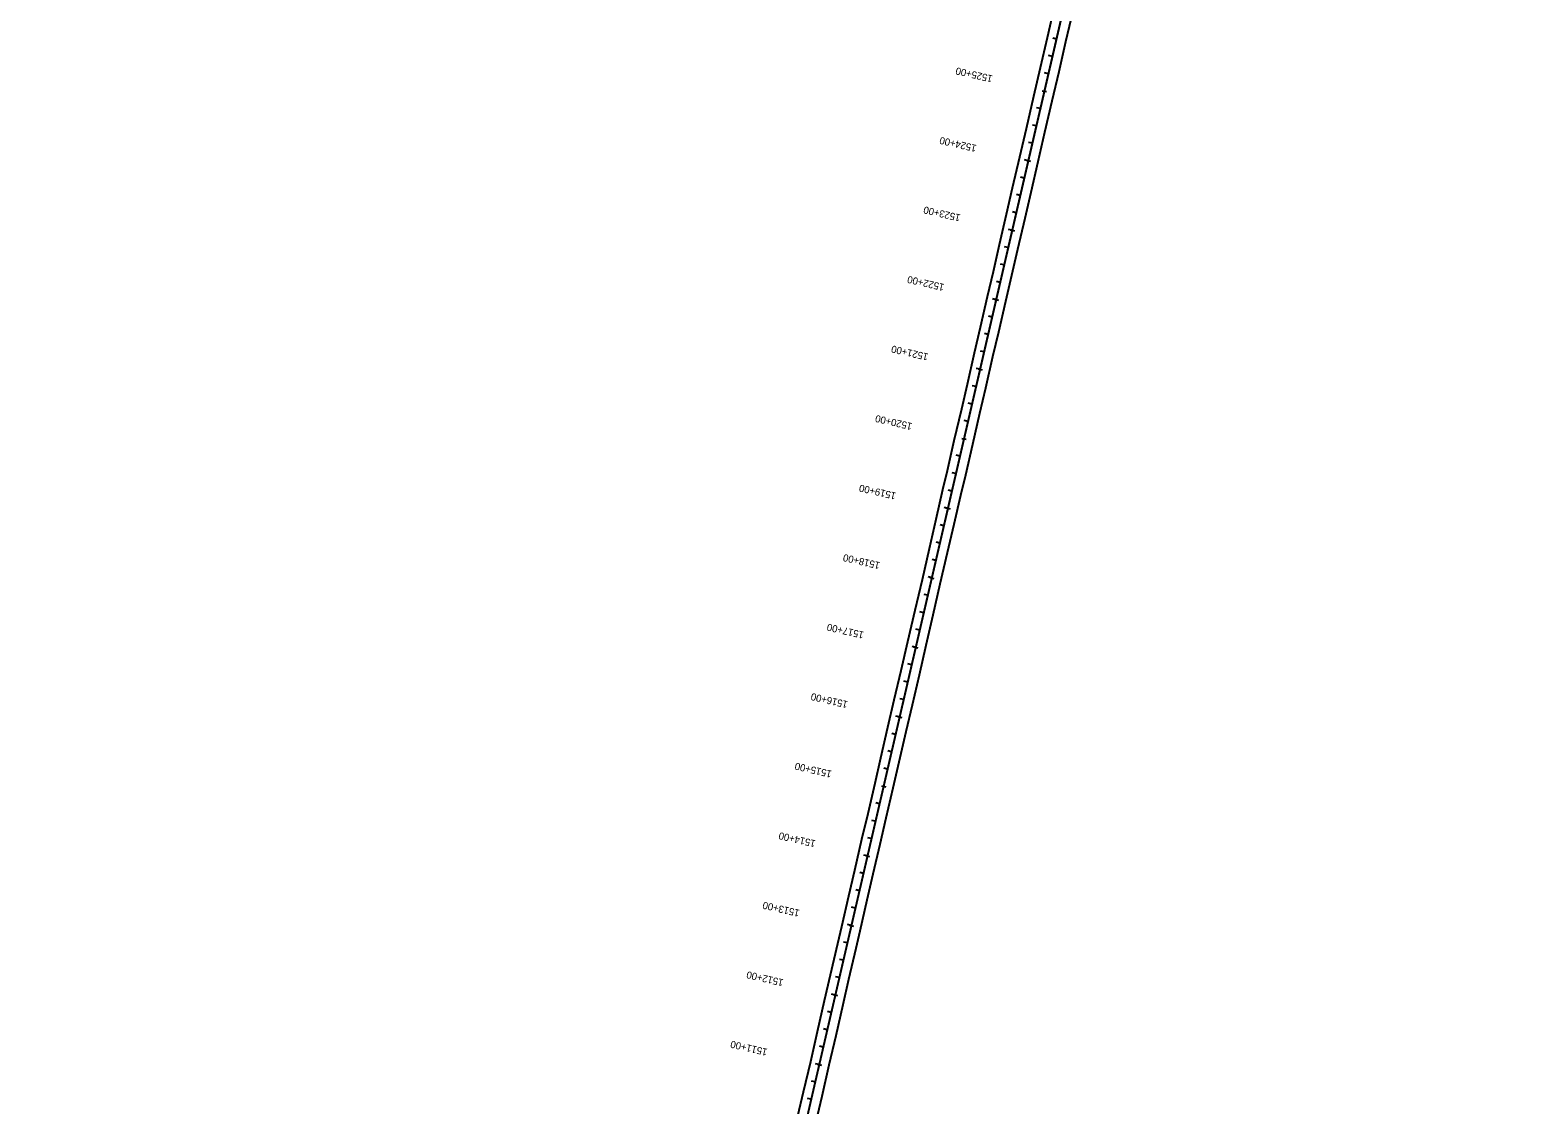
# Model space of a CAD drawing. Extents: x 21596470 to 21601942, y 8263806 to 8275912.
# Drawn here: x 21596601 to 21598714, y 8271376 to 8272882 of the extents above; entities that cross this region are included whole.
import ezdxf

# ---------------------------------------------------------------- set-up
doc = ezdxf.new("R2010")
doc.units = 0
for name, color, linetype in [('Level 1', 7, 'Continuous'), ('Level 20', 7, 'Continuous'), ('SurTxtLeaderLine', 7, 'Continuous'), ('SurTxtSurveyInformation', 7, 'Continuous'), ('wetNoteSoil', 7, 'Continuous')]:
    doc.layers.add(name, color=color, linetype=linetype)

msp = doc.modelspace()

# ---------------------------------------------------------------- linework, layer by layer
at = {"layer": 'Level 1'}
for p, q in [((21598019.8, 8272796.9), (21598025.8, 8272795.6)), ((21598000.3, 8272698.8), (21597994.9, 8272700.1)), ((21597977.7, 8272601.4), (21597972.4, 8272602.6)), ((21597955.2, 8272504), (21597949.9, 8272505.2)), ((21597932.6, 8272406.5), (21597927.3, 8272407.8)), ((21597907.1, 8272309.8), (21597913.1, 8272308.4)), ((21597887.6, 8272211.7), (21597882.2, 8272212.9)), ((21597865, 8272114.3), (21597859.7, 8272115.5)), ((21597842.5, 8272016.8), (21597837.2, 8272018.1)), ((21597819.9, 8271919.4), (21597814.6, 8271920.6)), ((21597794.4, 8271822.7), (21597800.4, 8271821.3)), ((21597774.9, 8271724.6), (21597769.5, 8271725.8)), ((21597752.3, 8271627.1), (21597747, 8271628.4)), ((21597729.8, 8271529.7), (21597724.5, 8271530.9)), ((21597707.2, 8271432.3), (21597701.9, 8271433.5))]:
    msp.add_line(p, q, dxfattribs=at)
at = {"layer": 'Level 20'}
for p, q in [((21596601.4, 8266652.3), (21598714.2, 8275785)), ((21596728.7, 8267202.6), (21598588.8, 8275242.6))]:
    msp.add_line(p, q, dxfattribs=at)
at = {"layer": 'SurTxtLeaderLine'}
msp.add_lwpolyline([(21597702.9, 8271352.7), (21597711.1, 8271388.2), (21597721, 8271431.7), (21597730.7, 8271473.1), (21597740.7, 8271516.5), (21597748.7, 8271551.9), (21597759, 8271595.4), (21597764.4, 8271619.7), (21597774.5, 8271663.2), (21597782.9, 8271699.4), (21597792.7, 8271741.1), (21597801.1, 8271777.8), (21597811, 8271820.1), (21597819.3, 8271856.4), (21597829, 8271898.9), (21597837.8, 8271936.2), (21597847.5, 8271978.2), (21597857.2, 8272020.1), (21597866.9, 8272062.3), (21597876.9, 8272105.9), (21597887.1, 8272149.6), (21597896.4, 8272189.7), (21597905.8, 8272230.2), (21597912.6, 8272258.8), (21597922.3, 8272301.6), (21597932.2, 8272344.9), (21597940.6, 8272380.6), (21597950.6, 8272424.3), (21597958.9, 8272459.1), (21597968.8, 8272502.2), (21597977.1, 8272538.3), (21597985.7, 8272575.1), (21597995.6, 8272618.1), (21598004.1, 8272654.8), (21598013.9, 8272697.5), (21598023.5, 8272738.7), (21598033.7, 8272782.6), (21598043.2, 8272823.7), (21598052.9, 8272865.9), (21598062.9, 8272908.8)], dxfattribs=at)
at = {"layer": 'SurTxtSurveyInformation'}
msp.add_lwpolyline([(21597677.4, 8271360.4), (21597685.2, 8271394.3), (21597695.2, 8271436.7), (21597704.9, 8271478.6), (21597714.8, 8271522), (21597722.9, 8271557.8), (21597733.3, 8271601.7), (21597739.1, 8271625.9), (21597748.9, 8271668.9), (21597757.1, 8271704.8), (21597767.1, 8271748.1), (21597775.6, 8271784.2), (21597785.4, 8271826.4), (21597793.6, 8271862.2), (21597803.5, 8271905.2), (21597812.3, 8271943.2), (21597822.2, 8271984.3), (21597831.5, 8272025), (21597841.7, 8272069), (21597851.7, 8272111.9), (21597861.7, 8272155.4), (21597871.2, 8272196.4), (21597880.6, 8272238.1), (21597886.9, 8272264.5), (21597896.5, 8272306.9), (21597907.1, 8272351.3), (21597914.9, 8272385.5), (21597925, 8272429.8), (21597933.1, 8272465.5), (21597943.1, 8272508.5), (21597951.2, 8272543.8), (21597959.7, 8272581.6), (21597969.4, 8272624), (21597978.2, 8272660.6), (21597988.3, 8272704.2), (21597997.5, 8272744), (21598007.9, 8272789.3), (21598017.1, 8272829.3), (21598027.1, 8272871.6), (21598036.9, 8272914.3)], dxfattribs=at)
at = {"layer": 'wetNoteSoil'}
for p, q in [((21598039.7, 8272869.3), (21598034.4, 8272870.5)), ((21598034.1, 8272845), (21598028.7, 8272846.2)), ((21598028.4, 8272820.6), (21598023.1, 8272821.8)), ((21598019.8, 8272796.9), (21598025.8, 8272795.6)), ((21598017.2, 8272771.9), (21598011.8, 8272773.1)), ((21598011.5, 8272747.5), (21598006.2, 8272748.8)), ((21598005.9, 8272723.2), (21598000.6, 8272724.4)), ((21597997.3, 8272699.5), (21598003.2, 8272698.1)), ((21597994.6, 8272674.5), (21597989.3, 8272675.7)), ((21597989, 8272650.1), (21597983.7, 8272651.3)), ((21597983.4, 8272625.7), (21597978, 8272627)), ((21597974.7, 8272602.1), (21597980.7, 8272600.7)), ((21597972.1, 8272577), (21597966.8, 8272578.3)), ((21597966.4, 8272552.7), (21597961.1, 8272553.9)), ((21597960.8, 8272528.3), (21597955.5, 8272529.6)), ((21597952.2, 8272504.7), (21597958.2, 8272503.3)), ((21597949.5, 8272479.6), (21597944.2, 8272480.8)), ((21597943.9, 8272455.3), (21597938.6, 8272456.5)), ((21597938.3, 8272430.9), (21597933, 8272432.1)), ((21597929.7, 8272407.2), (21597935.6, 8272405.8)), ((21597927, 8272382.2), (21597921.7, 8272383.4)), ((21597921.4, 8272357.8), (21597916, 8272359.1)), ((21597915.7, 8272333.5), (21597910.4, 8272334.7)), ((21597907.1, 8272309.8), (21597913.1, 8272308.4)), ((21597904.5, 8272284.8), (21597899.1, 8272286)), ((21597898.8, 8272260.4), (21597893.5, 8272261.6)), ((21597893.2, 8272236), (21597887.9, 8272237.3)), ((21597884.6, 8272212.4), (21597890.5, 8272211)), ((21597881.9, 8272187.3), (21597876.6, 8272188.6)), ((21597876.3, 8272163), (21597871, 8272164.2)), ((21597870.7, 8272138.6), (21597865.3, 8272139.8)), ((21597862, 8272114.9), (21597868, 8272113.6)), ((21597859.4, 8272089.9), (21597854.1, 8272091.1)), ((21597853.8, 8272065.5), (21597848.4, 8272066.8)), ((21597848.1, 8272041.2), (21597842.8, 8272042.4)), ((21597839.5, 8272017.5), (21597845.5, 8272016.1)), ((21597836.8, 8271992.5), (21597831.5, 8271993.7)), ((21597831.2, 8271968.1), (21597825.9, 8271969.3)), ((21597825.6, 8271943.8), (21597820.3, 8271945)), ((21597817, 8271920.1), (21597822.9, 8271918.7)), ((21597814.3, 8271895), (21597809, 8271896.3)), ((21597808.7, 8271870.7), (21597803.4, 8271871.9)), ((21597803, 8271846.3), (21597797.7, 8271847.6)), ((21597794.4, 8271822.7), (21597800.4, 8271821.3)), ((21597791.8, 8271797.6), (21597786.4, 8271798.9)), ((21597786.1, 8271773.3), (21597780.8, 8271774.5)), ((21597780.5, 8271748.9), (21597775.2, 8271750.1)), ((21597771.9, 8271725.2), (21597777.8, 8271723.9)), ((21597769.2, 8271700.2), (21597763.9, 8271701.4)), ((21597763.6, 8271675.8), (21597758.3, 8271677.1)), ((21597758, 8271651.5), (21597752.6, 8271652.7)), ((21597749.3, 8271627.8), (21597755.3, 8271626.4)), ((21597746.7, 8271602.8), (21597741.4, 8271604)), ((21597741.1, 8271578.4), (21597735.7, 8271579.6)), ((21597735.4, 8271554.1), (21597730.1, 8271555.3)), ((21597726.8, 8271530.4), (21597732.8, 8271529)), ((21597724.1, 8271505.3), (21597718.8, 8271506.6)), ((21597718.5, 8271481), (21597713.2, 8271482.2)), ((21597712.9, 8271456.6), (21597707.6, 8271457.9)), ((21597704.3, 8271433), (21597710.2, 8271431.6)), ((21597701.6, 8271407.9), (21597696.3, 8271409.1)), ((21597696, 8271383.6), (21597690.7, 8271384.8))]:
    msp.add_line(p, q, dxfattribs=at)

# ---------------------------------------------------------------- texts
at = {"layer": 'Level 1'}
for s, p in [('1525+00', (21597950.9, 8272818)), ('1520+00', (21597838.2, 8272330.9)), ('1515+00', (21597725.5, 8271843.8))]:
    msp.add_text(s, height=10.02, rotation=166.974, dxfattribs=at).set_placement(p)
at = {"layer": 'wetNoteSoil'}
for s, p in [('1525+00', (21597950.9, 8272818)), ('1524+00', (21597928.3, 8272720.6)), ('1523+00', (21597905.8, 8272623.2)), ('1522+00', (21597883.2, 8272525.8)), ('1521+00', (21597860.7, 8272428.3)), ('1520+00', (21597838.2, 8272330.9)), ('1519+00', (21597815.6, 8272233.5)), ('1518+00', (21597793.1, 8272136)), ('1517+00', (21597770.5, 8272038.6)), ('1516+00', (21597748, 8271941.2)), ('1515+00', (21597725.5, 8271843.8)), ('1514+00', (21597702.9, 8271746.3)), ('1513+00', (21597680.4, 8271648.9)), ('1512+00', (21597657.8, 8271551.5)), ('1511+00', (21597635.3, 8271454.1))]:
    msp.add_text(s, height=10.02, rotation=166.974, dxfattribs=at).set_placement(p)

doc.saveas('drawing.dxf')
